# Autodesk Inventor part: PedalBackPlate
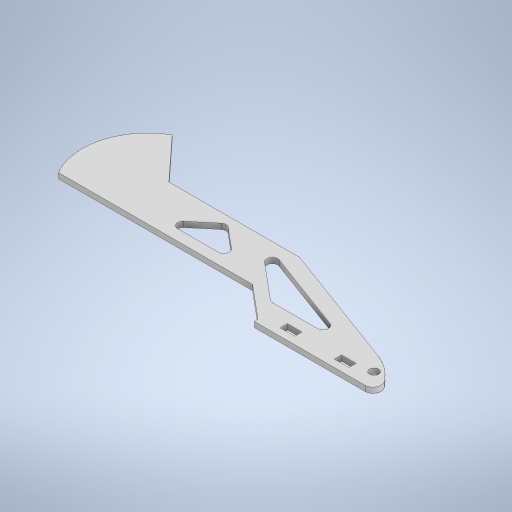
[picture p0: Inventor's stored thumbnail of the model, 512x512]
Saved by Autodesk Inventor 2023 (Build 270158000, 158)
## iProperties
Created: 2023-08
Part Number: PedalBackPlate
Material: Generic
Document SubType Name: Modeling
Designer: Admin
Density: 1 g/cm^3
Appearance: Default
Author: Admin
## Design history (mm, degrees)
sketch "Sketch3"
  geometry: L1 (66.296, -3.083)-(66.296, 3.05); L2 (149.285, 0.055)-(149.285, -42.344); L3 (68.896, 0.055)-(66.296, 0.055); L4 (66.296, 0.055)-(149.285, 0.055); L5 (149.285, -42.344)-(66.296, -42.344); L6 (2.221, 0.055)-(66.296, 0.055); L7 (22.6, 0.019)-(66.296, 0.055); L8 (66.296, -5.476)-(66.296, 0.055); L9 (66.296, -42.344)-(66.296, 0.055); L10 (66.296, 0.055)-(2.221, 0.055); L11 (0, 0)-(84.675, 0.07); L12 (84.675, 0.07)-(84.711, -43.19); L13 (84.711, -43.19)-(0.036, -43.261); L14 (0.036, -43.261)-(0, 0); L15 (66.296, 0.055)-(5.009, 0.004); L16 (66.296, 0.055)-(66.296, -1.945); L17 (66.296, -1.945)-(84.508, -17.19); L18 (14.721, -17.354)-(15.697, -17.757); L19 (15.697, -17.757)-(84.508, -43.19); L20 (178.504, -66.591)-(191.959, -17.101); L21 (191.959, -17.101)-(84.508, -17.19); L22 (84.508, -43.19)-(156.814, -43.13); L23 (156.814, -43.13)-(178.504, -66.591); L24 (28.607, -14)-(71.349, -14); L25 (71.349, -14)-(105.14, -42.287); L26 (105.14, -42.287)-(28.607, -14); L27 (101.183, -23.176)-(120.655, -39.478); L28 (120.655, -39.478)-(140.128, -23.144); L29 (140.128, -23.144)-(101.183, -23.176); L30 (120.655, -39.478)-(120.655, -23.16); L31 (26, -8)-(18, -8); L32 (18, -8)-(18, -4); L33 (18, -4)-(26, -4); L34 (26, -4)-(26, -8); L35 (22, -4)-(22, -8); L36 (48, -4)-(56, -4); L37 (56, -4)-(56, -8); L38 (56, -8)-(48, -8); L39 (48, -8)-(48, -4); L40 (52, -4)-(52, -8); C1 r 2.5 at (9.007, -8.993); A1 r 31.175 centre (26.616, 11.462) between (1.477, -6.974) and (14.721, -17.354); A2 r 4.385 centre (5.013, -4.381) between (5.009, 0.004) and (1.477, -6.974); A3 r 36.14 centre (160.658, -35.165) between (178.504, -66.591) and (191.959, -17.101); 3 further points; 1 other entity
  constraints: 64 end point, 10 parallel, 10 point on line, 6 midpoint, 6 point on circle, 5 horizontal, 4 centre point, 4 vertical, 3 tangent, 2 collinear, 2 equal length, 2 perpendicular, 1 coincident, 1 vertical alignment, 3 other
  dimensions: "d15" = 2.6 distance of L3.end L3.start; "d16" = 42.39919 distance between parallel lines of L4 L5; "d202" = 43.26069 distance from line of L11 L19.end; "d239" = 84.50764 horizontal distance of point (0, 0) L19.end; "d240" = 43.19037 vertical distance of point (0, 0) L19.end; "d241" = 2 distance from line of L3 L16.end; "d242" = 5 diameter of C1; "d245" = 9 distance from line of L14 C1.centre; "d248" = 9 distance from line of L11 C1.centre; "d285" = 6 distance between parallel lines of L17 L25; "d321" = 26 distance between parallel lines of L22 L21; "d400" = 6 distance between parallel lines of L21 L29; "d455" = 4 distance between parallel lines of L31 L33; "d456" = 8 distance between parallel lines of L32 L34; "d464" = 4 distance from line of L33 point (0, 0); "d465" = 18 distance from line of point (0, 0) L32; "d482" = 14 distance from line of point (0, 0) L24; "d540" = 15.20893 horizontal distance of point (0, 0) point (15.209, -17.556); "d541" = 17.3543 vertical distance of point (0, 0) L18.start; "d558" = 8 distance between parallel lines of L19 L26; "d565" = 30 distance between parallel lines of L35 L40
extrude "Extrusion1" new body sketch "Sketch3" distance "d450" = 3; taper "d451" = 0 deg
fillet "Fillet1" dims "d454" = 3
body "Solid1"
node "Image2"
